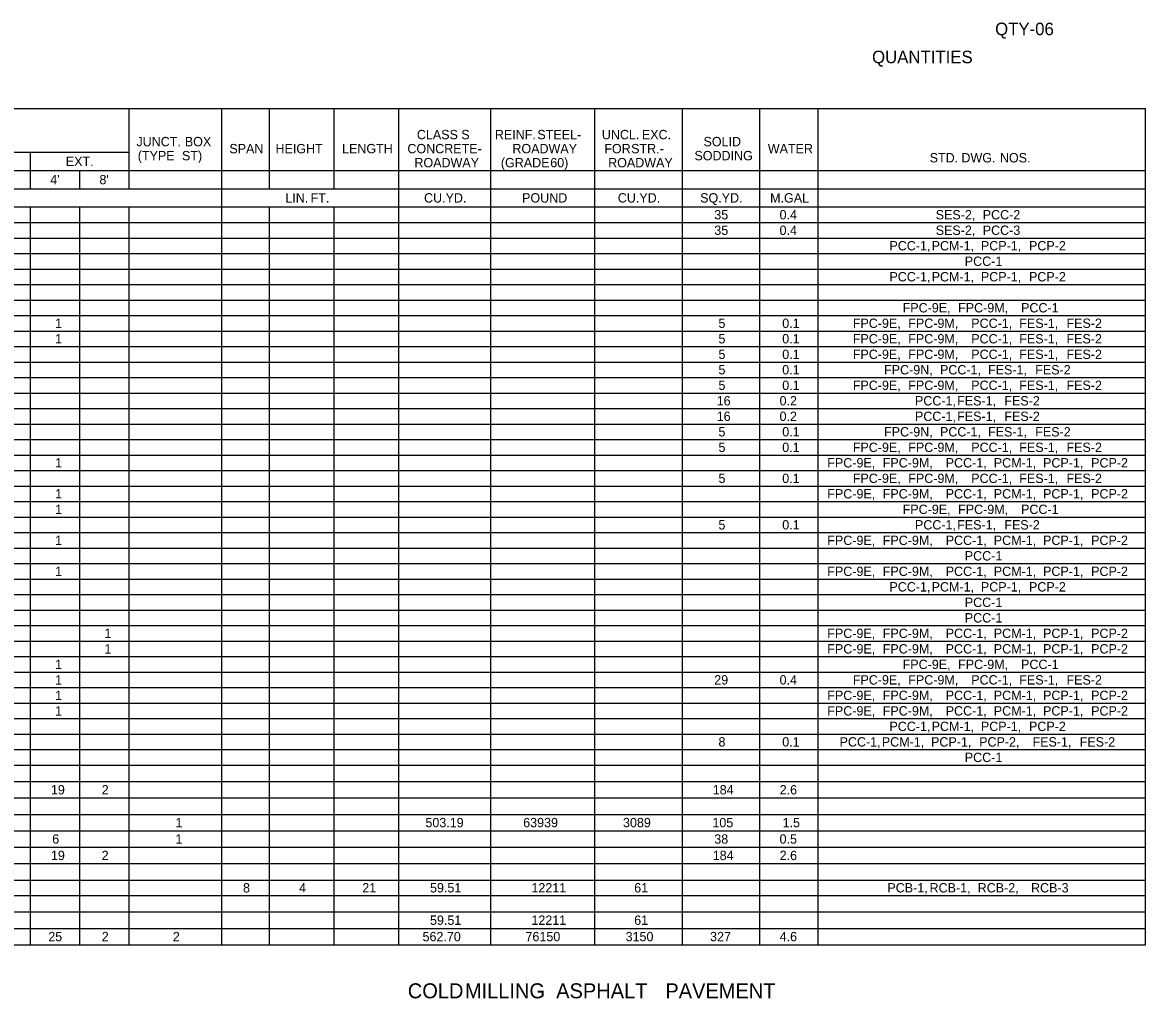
# Model space of a CAD drawing. Extents: x 1226561 to 1228164, y 151309 to 152305.
# Drawn here: x 1227627 to 1228152, y 151849 to 152305 of the extents above; entities that cross this region are included whole.
import ezdxf

# ---------------------------------------------------------------- set-up
doc = ezdxf.new("R2010")
doc.units = 0
doc.layers.add('R_Border', color=7, linetype='Continuous')
doc.layers.add('R_Dimension', color=7, linetype='Continuous')

msp = doc.modelspace()

# ---------------------------------------------------------------- linework, layer by layer
at = {"layer": 'R_Dimension'}
for p, q in [((1226564.67, 152265.3), (1228152.39, 152265.3)), ((1227677.21, 152227.8), (1227677.21, 152265.3)), ((1227720.68, 151874.5), (1227720.68, 152265.3)), ((1227742.84, 152227.8), (1227742.84, 152265.3)), ((1227773.1, 152227.8), (1227773.1, 152265.3)), ((1227803.35, 151874.5), (1227803.35, 152265.3)), ((1227846.4, 151874.5), (1227846.4, 152265.3)), ((1227894.98, 151874.5), (1227894.98, 152265.3)), ((1227935.9, 151874.5), (1227935.9, 152265.3)), ((1227972.12, 151874.5), (1227972.12, 152265.3)), ((1227999.4, 151874.5), (1227999.4, 152265.3)), ((1228152.39, 151874.5), (1228152.39, 152265.3)), ((1227467.53, 152244.85), (1227677.21, 152244.85)), ((1227631.18, 152227.8), (1227631.18, 152244.85)), ((1227312.25, 152236.32), (1228152.39, 152236.32)), ((1227654.19, 152227.8), (1227654.19, 152236.32)), ((1226850.27, 152227.8), (1228152.39, 152227.8)), ((1227467.53, 152227.8), (1228045.42, 152227.8)), ((1226564.67, 152219.27), (1228152.39, 152219.27)), ((1227631.18, 151874.5), (1227631.18, 152219.27)), ((1227654.19, 151874.5), (1227654.19, 152219.27)), ((1227677.21, 151874.5), (1227677.21, 152219.27)), ((1227742.84, 151874.5), (1227742.84, 152219.27)), ((1227773.1, 151874.5), (1227773.1, 152219.27)), ((1227999.4, 152219.27), (1228152.39, 152219.27)), ((1226564.67, 152212.03), (1228152.39, 152212.03)), ((1226564.67, 152204.78), (1228152.39, 152204.78)), ((1226564.67, 152197.54), (1228152.39, 152197.54)), ((1226564.67, 152190.29), (1228152.39, 152190.29)), ((1226564.67, 152183.05), (1228152.39, 152183.05)), ((1226564.67, 152175.8), (1228152.39, 152175.8)), ((1226564.67, 152168.56), (1228152.39, 152168.56)), ((1226564.67, 152161.31), (1228152.39, 152161.31)), ((1226564.67, 152154.07), (1228152.39, 152154.07)), ((1226564.67, 152146.82), (1228152.39, 152146.82)), ((1226564.67, 152139.58), (1228152.39, 152139.58)), ((1226564.67, 152132.33), (1228152.39, 152132.33)), ((1226564.67, 152125.09), (1228152.39, 152125.09)), ((1226564.67, 152117.84), (1228152.39, 152117.84)), ((1226564.67, 152110.6), (1228152.39, 152110.6)), ((1226564.67, 152103.35), (1228152.39, 152103.35)), ((1226564.67, 152096.11), (1228152.39, 152096.11)), ((1226564.67, 152088.86), (1228152.39, 152088.86)), ((1226564.67, 152081.62), (1228152.39, 152081.62)), ((1226564.67, 152074.37), (1228152.39, 152074.37)), ((1226564.67, 152067.13), (1228152.39, 152067.13)), ((1226564.67, 152059.88), (1228152.39, 152059.88)), ((1226564.67, 152052.64), (1228152.39, 152052.64)), ((1226564.67, 152045.39), (1228152.39, 152045.39)), ((1226564.67, 152038.15), (1228152.39, 152038.15)), ((1226564.67, 152030.9), (1228152.39, 152030.9)), ((1226564.67, 152023.66), (1228152.39, 152023.66)), ((1226564.67, 152016.41), (1228152.39, 152016.41)), ((1226564.67, 152009.17), (1228152.39, 152009.17)), ((1226564.67, 152001.92), (1228152.39, 152001.92)), ((1226564.67, 151994.68), (1228152.39, 151994.68)), ((1226564.67, 151987.43), (1228152.39, 151987.43)), ((1226564.67, 151980.19), (1228152.39, 151980.19)), ((1226564.67, 151972.94), (1228152.39, 151972.94)), ((1226564.67, 151965.7), (1228152.39, 151965.7)), ((1226564.67, 151958.45), (1228152.39, 151958.45)), ((1226564.67, 151950.78), (1228152.39, 151950.78)), ((1226564.67, 151943.11), (1228152.39, 151943.11)), ((1226564.67, 151935.44), (1228152.39, 151935.44)), ((1227631.18, 151912.43), (1227631.18, 151935.44)), ((1227654.19, 151912.43), (1227654.19, 151935.44)), ((1227677.21, 151912.43), (1227677.21, 151935.44)), ((1227720.68, 151912.43), (1227720.68, 151935.44)), ((1227720.68, 151912.43), (1227720.68, 151935.44)), ((1227742.84, 151912.43), (1227742.84, 151935.44)), ((1227773.1, 151912.43), (1227773.1, 151935.44)), ((1227803.35, 151912.43), (1227803.35, 151935.44)), ((1227846.4, 151912.43), (1227846.4, 151935.44)), ((1227894.98, 151912.43), (1227894.98, 151935.44)), ((1227935.9, 151912.43), (1227935.9, 151935.44)), ((1227972.12, 151912.43), (1227972.12, 151935.44)), ((1227999.4, 151912.43), (1227999.4, 151935.44)), ((1226564.67, 151927.77), (1228152.39, 151927.77)), ((1226564.67, 151920.1), (1228152.39, 151920.1)), ((1226564.67, 151912.43), (1228152.39, 151912.43)), ((1226564.67, 151904.75), (1228152.39, 151904.75)), ((1227631.18, 151874.5), (1227631.18, 151904.75)), ((1227654.19, 151874.5), (1227654.19, 151904.75)), ((1227677.21, 151874.5), (1227677.21, 151904.75)), ((1227720.68, 151874.5), (1227720.68, 151904.75)), ((1227720.68, 151874.5), (1227720.68, 151904.75)), ((1227742.84, 151874.5), (1227742.84, 151904.75)), ((1227773.1, 151874.5), (1227773.1, 151904.75)), ((1227803.35, 151874.5), (1227803.35, 151904.75)), ((1227846.4, 151874.5), (1227846.4, 151904.75)), ((1227894.98, 151874.5), (1227894.98, 151904.75)), ((1227935.9, 151874.5), (1227935.9, 151904.75)), ((1227972.12, 151874.5), (1227972.12, 151904.75)), ((1227999.4, 151874.5), (1227999.4, 151904.75)), ((1226564.67, 151897.51), (1228152.39, 151897.51)), ((1226564.67, 151889.84), (1228152.39, 151889.84)), ((1226564.67, 151882.17), (1228152.39, 151882.17)), ((1226564.67, 151874.5), (1228152.39, 151874.5))]:
    msp.add_line(p, q, dxfattribs=at)

# ---------------------------------------------------------------- texts
at = {"layer": 'R_Border'}
for s, height, p in [('QTY-06', 5.861, (1228082.08, 152299.55)), ('QUANTITIES', 5.862, (1228024.56, 152286.45))]:
    msp.add_text(s, height=height, dxfattribs=at).set_placement(p)
at = {"layer": 'R_Dimension'}
for s, height, p in [('JUNCT.', 4.371, (1227680.68, 152247.64)), (' BOX', 4.371, (1227701.68, 152247.64)), ('CLASS', 4.371, (1227811.78, 152250.92)), (' S', 4.371, (1227830.92, 152250.92)), ('REINF.', 4.371, (1227848.23, 152250.92)), (' STEEL-', 4.371, (1227866.47, 152250.92)), ('UNCL.', 4.371, (1227898.25, 152250.92)), (' EXC.', 4.371, (1227915.32, 152250.92)), ('SOLID', 4.371, (1227945.76, 152247.64)), ('SPAN', 4.371, (1227724.13, 152244.36)), ('HEIGHT', 4.371, (1227745.68, 152244.36)), ('LENGTH', 4.371, (1227776.8, 152244.36)), ('CONCRETE-', 4.371, (1227807.36, 152244.36)), ('ROADWAY', 4.371, (1227856.44, 152244.36)), ('FOR', 4.371, (1227899.4, 152244.36)), (' STR.-', 4.371, (1227910.31, 152244.36)), ('WATER', 4.371, (1227975.83, 152244.36)), ('EXT.', 4.371, (1227647.65, 152238.4)), ('(TYPE', 4.371, (1227681.32, 152241.09)), ('  ST)', 4.371, (1227698.73, 152241.09)), ('ROADWAY', 4.371, (1227810.63, 152237.81)), ('(GRADE', 4.371, (1227851.04, 152237.81)), (' 60)', 4.371, (1227872.51, 152237.81)), ('ROADWAY', 4.371, (1227901.19, 152237.81)), ('SODDING', 4.371, (1227941.53, 152241.09)), ('STD.', 4.371, (1228051.49, 152240.1)), (' DWG.', 4.371, (1228064.71, 152240.1)), (' NOS.', 4.371, (1228082.71, 152240.1)), ("4'", 4.371, (1227640.38, 152229.87)), ("8'", 4.371, (1227663.39, 152229.87)), ('LIN.', 4.371, (1227750.3, 152221.35)), (' FT.', 4.371, (1227760.48, 152221.35)), ('CU.YD.', 4.371, (1227815.14, 152221.35)), ('POUND', 4.371, (1227860.97, 152221.35)), ('CU.YD.', 4.371, (1227905.7, 152221.35)), ('SQ.YD.', 4.371, (1227944.2, 152221.35)), ('M.GAL', 4.371, (1227976.91, 152221.35)), ('35', 4.371, (1227950.81, 152213.47)), ('0.4', 4.371, (1227981.32, 152213.47)), ('SES-2,', 4.371, (1228054.3, 152213.47)), (' PCC-2', 4.371, (1228074.67, 152213.47)), ('35', 4.371, (1227950.81, 152206.22)), ('0.4', 4.371, (1227981.32, 152206.22)), ('SES-2,', 4.371, (1228054.3, 152206.22)), (' PCC-3', 4.371, (1228074.67, 152206.22)), ('PCC-1,', 4.371, (1228032.68, 152198.98)), (' PCM-1,', 4.371, (1228050.79, 152198.98)), (' PCP-1,', 4.371, (1228073.81, 152198.98)), (' PCP-2', 4.371, (1228096.29, 152198.98)), ('PCC-1', 4.371, (1228067.91, 152191.73)), ('PCC-1,', 4.371, (1228032.68, 152184.49)), (' PCM-1,', 4.371, (1228050.79, 152184.49)), (' PCP-1,', 4.371, (1228073.81, 152184.49)), (' PCP-2', 4.371, (1228096.29, 152184.49)), ('FPC-9E,', 4.371, (1228038.86, 152170)), (' FPC-9M,', 4.371, (1228063.16, 152170)), (' PCC-1', 4.371, (1228092.59, 152170)), ('1', 4.37, (1227642.68, 152162.75)), ('5', 4.37, (1227952.77, 152162.75)), ('0.1', 4.371, (1227982.56, 152162.75)), ('FPC-9E,', 4.371, (1228015.56, 152162.75)), (' FPC-9M,', 4.371, (1228039.86, 152162.75)), (' PCC-1,', 4.371, (1228069.29, 152162.75)), (' FES-1,', 4.371, (1228091.76, 152162.75)), (' FES-2', 4.371, (1228113.82, 152162.75)), ('1', 4.37, (1227642.68, 152155.51)), ('5', 4.37, (1227952.77, 152155.51)), ('0.1', 4.371, (1227982.56, 152155.51)), ('FPC-9E,', 4.371, (1228015.56, 152155.51)), (' FPC-9M,', 4.371, (1228039.86, 152155.51)), (' PCC-1,', 4.371, (1228069.29, 152155.51)), (' FES-1,', 4.371, (1228091.76, 152155.51)), (' FES-2', 4.371, (1228113.82, 152155.51)), ('5', 4.37, (1227952.77, 152148.26)), ('0.1', 4.371, (1227982.56, 152148.26)), ('FPC-9E,', 4.371, (1228015.56, 152148.26)), (' FPC-9M,', 4.371, (1228039.86, 152148.26)), (' PCC-1,', 4.371, (1228069.29, 152148.26)), (' FES-1,', 4.371, (1228091.76, 152148.26)), (' FES-2', 4.371, (1228113.82, 152148.26)), ('5', 4.37, (1227952.77, 152141.02)), ('0.1', 4.371, (1227982.56, 152141.02)), ('FPC-9N,', 4.371, (1228030.17, 152141.02)), (' PCC-1,', 4.371, (1228054.68, 152141.02)), (' FES-1,', 4.371, (1228077.15, 152141.02)), (' FES-2', 4.371, (1228099.21, 152141.02)), ('5', 4.37, (1227952.77, 152133.77)), ('0.1', 4.371, (1227982.56, 152133.77)), ('FPC-9E,', 4.371, (1228015.56, 152133.77)), (' FPC-9M,', 4.371, (1228039.86, 152133.77)), (' PCC-1,', 4.371, (1228069.29, 152133.77)), (' FES-1,', 4.371, (1228091.76, 152133.77)), (' FES-2', 4.371, (1228113.82, 152133.77)), ('16', 4.371, (1227951.93, 152126.53)), ('0.2', 4.371, (1227981.32, 152126.53)), ('PCC-1,', 4.371, (1228044.61, 152126.53)), (' FES-1,', 4.371, (1228062.71, 152126.53)), (' FES-2', 4.371, (1228084.77, 152126.53)), ('16', 4.371, (1227951.93, 152119.28)), ('0.2', 4.371, (1227981.32, 152119.28)), ('PCC-1,', 4.371, (1228044.61, 152119.28)), (' FES-1,', 4.371, (1228062.71, 152119.28)), (' FES-2', 4.371, (1228084.77, 152119.28)), ('5', 4.37, (1227952.77, 152112.04)), ('0.1', 4.371, (1227982.56, 152112.04)), ('FPC-9N,', 4.371, (1228030.17, 152112.04)), (' PCC-1,', 4.371, (1228054.68, 152112.04)), (' FES-1,', 4.371, (1228077.15, 152112.04)), (' FES-2', 4.371, (1228099.21, 152112.04)), ('5', 4.37, (1227952.77, 152104.79)), ('0.1', 4.371, (1227982.56, 152104.79)), ('FPC-9E,', 4.371, (1228015.56, 152104.79)), (' FPC-9M,', 4.371, (1228039.86, 152104.79)), (' PCC-1,', 4.371, (1228069.29, 152104.79)), (' FES-1,', 4.371, (1228091.76, 152104.79)), (' FES-2', 4.371, (1228113.82, 152104.79)), ('1', 4.37, (1227642.68, 152097.55)), ('FPC-9E,', 4.371, (1228003.63, 152097.55)), (' FPC-9M,', 4.371, (1228027.93, 152097.55)), (' PCC-1,', 4.371, (1228057.36, 152097.55)), (' PCM-1,', 4.371, (1228079.84, 152097.55)), (' PCP-1,', 4.371, (1228102.86, 152097.55)), (' PCP-2', 4.371, (1228125.34, 152097.55)), ('5', 4.37, (1227952.77, 152090.3)), ('0.1', 4.371, (1227982.56, 152090.3)), ('FPC-9E,', 4.371, (1228015.56, 152090.3)), (' FPC-9M,', 4.371, (1228039.86, 152090.3)), (' PCC-1,', 4.371, (1228069.29, 152090.3)), (' FES-1,', 4.371, (1228091.76, 152090.3)), (' FES-2', 4.371, (1228113.82, 152090.3)), ('1', 4.37, (1227642.68, 152083.06)), ('FPC-9E,', 4.371, (1228003.63, 152083.06)), (' FPC-9M,', 4.371, (1228027.93, 152083.06)), (' PCC-1,', 4.371, (1228057.36, 152083.06)), (' PCM-1,', 4.371, (1228079.84, 152083.06)), (' PCP-1,', 4.371, (1228102.86, 152083.06)), (' PCP-2', 4.371, (1228125.34, 152083.06)), ('1', 4.37, (1227642.68, 152075.81)), ('FPC-9E,', 4.371, (1228038.86, 152075.81)), (' FPC-9M,', 4.371, (1228063.16, 152075.81)), (' PCC-1', 4.371, (1228092.59, 152075.81)), ('5', 4.37, (1227952.77, 152068.57)), ('0.1', 4.371, (1227982.56, 152068.57)), ('PCC-1,', 4.371, (1228044.61, 152068.57)), (' FES-1,', 4.371, (1228062.71, 152068.57)), (' FES-2', 4.371, (1228084.77, 152068.57)), ('1', 4.37, (1227642.68, 152061.32)), ('FPC-9E,', 4.371, (1228003.63, 152061.32)), (' FPC-9M,', 4.371, (1228027.93, 152061.32)), (' PCC-1,', 4.371, (1228057.36, 152061.32)), (' PCM-1,', 4.371, (1228079.84, 152061.32)), (' PCP-1,', 4.371, (1228102.86, 152061.32)), (' PCP-2', 4.371, (1228125.34, 152061.32)), ('PCC-1', 4.371, (1228067.91, 152054.08)), ('1', 4.37, (1227642.68, 152046.83)), ('FPC-9E,', 4.371, (1228003.63, 152046.83)), (' FPC-9M,', 4.371, (1228027.93, 152046.83)), (' PCC-1,', 4.371, (1228057.36, 152046.83)), (' PCM-1,', 4.371, (1228079.84, 152046.83)), (' PCP-1,', 4.371, (1228102.86, 152046.83)), (' PCP-2', 4.371, (1228125.34, 152046.83)), ('PCC-1,', 4.371, (1228032.68, 152039.59)), (' PCM-1,', 4.371, (1228050.79, 152039.59)), (' PCP-1,', 4.371, (1228073.81, 152039.59)), (' PCP-2', 4.371, (1228096.29, 152039.59)), ('PCC-1', 4.371, (1228067.91, 152032.34)), ('PCC-1', 4.371, (1228067.91, 152025.1)), ('1', 4.37, (1227665.7, 152017.85)), ('FPC-9E,', 4.371, (1228003.63, 152017.85)), (' FPC-9M,', 4.371, (1228027.93, 152017.85)), (' PCC-1,', 4.371, (1228057.36, 152017.85)), (' PCM-1,', 4.371, (1228079.84, 152017.85)), (' PCP-1,', 4.371, (1228102.86, 152017.85)), (' PCP-2', 4.371, (1228125.34, 152017.85)), ('1', 4.37, (1227665.7, 152010.61)), ('FPC-9E,', 4.371, (1228003.63, 152010.61)), (' FPC-9M,', 4.371, (1228027.93, 152010.61)), (' PCC-1,', 4.371, (1228057.36, 152010.61)), (' PCM-1,', 4.371, (1228079.84, 152010.61)), (' PCP-1,', 4.371, (1228102.86, 152010.61)), (' PCP-2', 4.371, (1228125.34, 152010.61)), ('1', 4.37, (1227642.68, 152003.36)), ('FPC-9E,', 4.371, (1228038.86, 152003.36)), (' FPC-9M,', 4.371, (1228063.16, 152003.36)), (' PCC-1', 4.371, (1228092.59, 152003.36)), ('1', 4.37, (1227642.68, 151996.12)), ('29', 4.371, (1227950.79, 151996.12)), ('0.4', 4.371, (1227981.32, 151996.12)), ('FPC-9E,', 4.371, (1228015.56, 151996.12)), (' FPC-9M,', 4.371, (1228039.86, 151996.12)), (' PCC-1,', 4.371, (1228069.29, 151996.12)), (' FES-1,', 4.371, (1228091.76, 151996.12)), (' FES-2', 4.371, (1228113.82, 151996.12)), ('1', 4.37, (1227642.68, 151988.87)), ('FPC-9E,', 4.371, (1228003.63, 151988.87)), (' FPC-9M,', 4.371, (1228027.93, 151988.87)), (' PCC-1,', 4.371, (1228057.36, 151988.87)), (' PCM-1,', 4.371, (1228079.84, 151988.87)), (' PCP-1,', 4.371, (1228102.86, 151988.87)), (' PCP-2', 4.371, (1228125.34, 151988.87)), ('1', 4.37, (1227642.68, 151981.63)), ('FPC-9E,', 4.371, (1228003.63, 151981.63)), (' FPC-9M,', 4.371, (1228027.93, 151981.63)), (' PCC-1,', 4.371, (1228057.36, 151981.63)), (' PCM-1,', 4.371, (1228079.84, 151981.63)), (' PCP-1,', 4.371, (1228102.86, 151981.63)), (' PCP-2', 4.371, (1228125.34, 151981.63)), ('PCC-1,', 4.371, (1228032.68, 151974.38)), (' PCM-1,', 4.371, (1228050.79, 151974.38)), (' PCP-1,', 4.371, (1228073.81, 151974.38)), (' PCP-2', 4.371, (1228096.29, 151974.38)), ('8', 4.37, (1227952.77, 151967.14)), ('0.1', 4.371, (1227982.56, 151967.14)), ('PCC-1,', 4.371, (1228009.38, 151967.14)), (' PCM-1,', 4.371, (1228027.49, 151967.14)), (' PCP-1,', 4.371, (1228050.51, 151967.14)), (' PCP-2,', 4.371, (1228072.99, 151967.14)), (' FES-1,', 4.371, (1228097.94, 151967.14)), (' FES-2', 4.371, (1228120, 151967.14)), ('PCC-1', 4.371, (1228067.91, 151959.89)), ('19', 4.371, (1227640.71, 151944.76)), ('2', 4.37, (1227664.46, 151944.76)), ('184', 4.371, (1227950.08, 151944.76)), ('2.6', 4.371, (1227981.37, 151944.76)), ('1', 4.37, (1227698.94, 151929.42)), ('503.19', 4.371, (1227815.77, 151929.42)), ('63939', 4.371, (1227861.48, 151929.42)), ('3089', 4.371, (1227908.13, 151929.42)), ('105', 4.371, (1227949.91, 151929.42)), ('1.5', 4.371, (1227982.73, 151929.42)), ('6', 4.37, (1227641.33, 151921.75)), ('1', 4.37, (1227698.94, 151921.75)), ('38', 4.371, (1227950.81, 151921.75)), ('0.5', 4.371, (1227981.32, 151921.75)), ('19', 4.371, (1227640.71, 151914.08)), ('2', 4.37, (1227664.46, 151914.08)), ('184', 4.371, (1227950.08, 151914.08)), ('2.6', 4.371, (1227981.37, 151914.08)), ('8', 4.37, (1227730.52, 151898.95)), ('4', 4.37, (1227756.73, 151898.95)), ('21', 4.371, (1227786.26, 151898.95)), ('59.51', 4.371, (1227817.92, 151898.95)), ('12211', 4.371, (1227865.32, 151898.95)), ('61', 4.371, (1227913.37, 151898.95)), ('PCB-1,', 4.371, (1228031.72, 151898.95)), (' RCB-1,', 4.371, (1228049.82, 151898.95)), (' RCB-2,', 4.371, (1228072.3, 151898.95)), (' RCB-3', 4.371, (1228097.25, 151898.95)), ('59.51', 4.371, (1227817.92, 151883.82)), ('12211', 4.371, (1227865.32, 151883.82)), ('61', 4.371, (1227913.37, 151883.82)), ('25', 4.371, (1227639.48, 151876.15)), ('2', 4.37, (1227664.46, 151876.15)), ('2', 4.37, (1227697.7, 151876.15)), ('562.70', 4.371, (1227814.43, 151876.15)), ('76150', 4.371, (1227862.55, 151876.15)), ('3150', 4.371, (1227909.36, 151876.15)), ('327', 4.371, (1227948.85, 151876.15)), ('4.6', 4.371, (1227981.37, 151876.15)), ('COLD', 7, (1227807.54, 151849.49)), (' MILLING', 7, (1227831.63, 151849.49)), (' ASPHALT', 7, (1227874.29, 151849.49)), (' PAVEMENT', 7, (1227925.33, 151849.49))]:
    msp.add_text(s, height=height, dxfattribs=at).set_placement(p)

doc.saveas('drawing.dxf')
